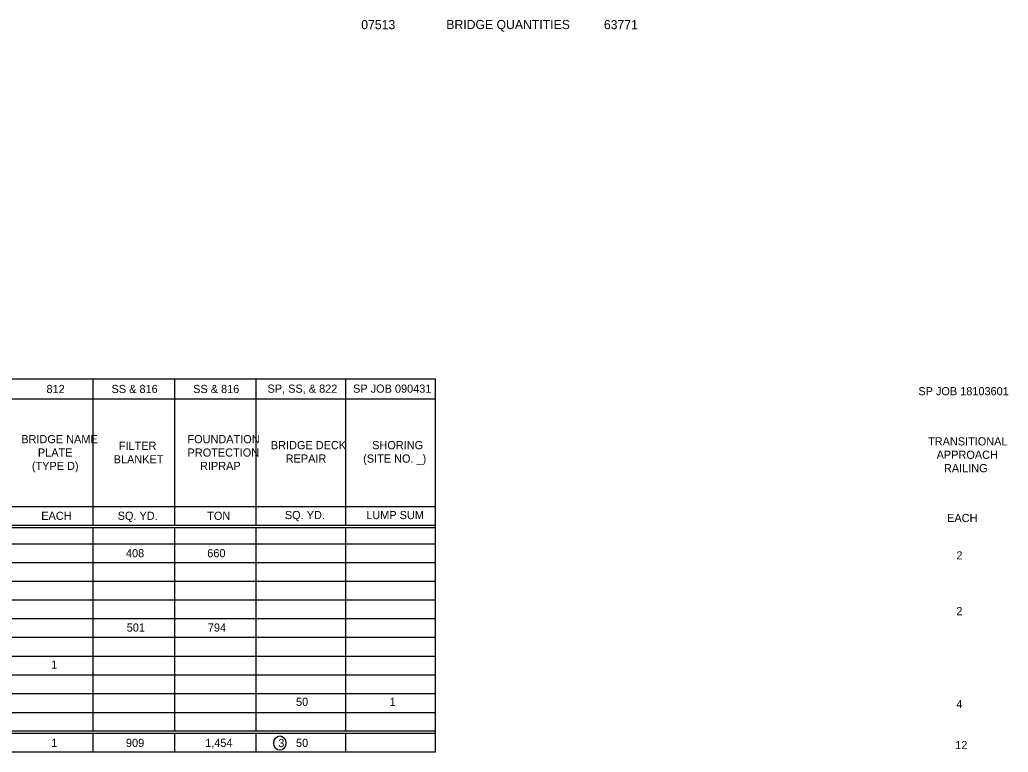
# Model space of a CAD drawing. Extents: x 1667526.8 to 1667564.8, y 551427.6 to 551446.9.
# Drawn here: x 1667545.82 to 1667560.96, y 551435.73 to 551446.94 of the extents above; entities that cross this region are included whole.
import ezdxf

# ---------------------------------------------------------------- set-up
doc = ezdxf.new("R2010")
doc.units = 0
doc.layers.add('Level 4', color=7, linetype='Continuous')
doc.layers.add('R_Border', color=7, linetype='Continuous')

msp = doc.modelspace()

# ---------------------------------------------------------------- linework, layer by layer
at = {"layer": 'Level 4'}
for p, q in [((1667552.188, 551441.439), (1667526.829, 551441.439)), ((1667546.945, 551439.206), (1667546.945, 551441.439)), ((1667548.195, 551439.206), (1667548.195, 551441.439)), ((1667549.445, 551439.206), (1667549.445, 551441.439)), ((1667550.816, 551439.206), (1667550.816, 551441.439)), ((1667552.188, 551435.729), (1667552.188, 551441.439)), ((1667530.881, 551441.142), (1667552.188, 551441.142)), ((1667531.616, 551439.493), (1667552.188, 551439.493)), ((1667526.829, 551439.206), (1667552.188, 551439.206)), ((1667526.829, 551439.168), (1667552.188, 551439.168)), ((1667546.945, 551436.054), (1667546.945, 551439.168)), ((1667548.195, 551436.054), (1667548.195, 551439.168)), ((1667549.445, 551436.054), (1667549.445, 551439.168)), ((1667550.816, 551436.054), (1667550.816, 551439.168)), ((1667527.984, 551438.92), (1667552.188, 551438.92)), ((1667527.984, 551438.633), (1667552.188, 551438.633)), ((1667527.984, 551438.347), (1667552.188, 551438.347)), ((1667527.984, 551438.06), (1667552.188, 551438.06)), ((1667552.188, 551437.773), (1667527.984, 551437.773)), ((1667552.188, 551437.487), (1667527.984, 551437.487)), ((1667527.984, 551437.2), (1667552.188, 551437.2)), ((1667527.984, 551436.914), (1667552.188, 551436.914)), ((1667527.984, 551436.627), (1667552.188, 551436.627)), ((1667527.984, 551436.34), (1667552.188, 551436.34)), ((1667552.188, 551436.054), (1667526.829, 551436.054)), ((1667552.188, 551436.016), (1667528.635, 551436.016)), ((1667546.945, 551435.729), (1667546.945, 551436.016)), ((1667548.195, 551435.729), (1667548.195, 551436.016)), ((1667549.445, 551435.729), (1667549.445, 551436.016)), ((1667550.816, 551435.729), (1667550.816, 551436.016)), ((1667552.188, 551435.729), (1667526.829, 551435.729))]:
    msp.add_line(p, q, dxfattribs=at)
msp.add_ellipse((1667549.806, 551435.869), major_axis=(0, 0.11), ratio=0.84, dxfattribs=at)

# ---------------------------------------------------------------- texts
for s, p in [('812', (1667546.232, 551441.228)), ('SS & 816', (1667547.228, 551441.228)), ('SS & 816', (1667548.478, 551441.228)), ('SP, SS, & 822', (1667549.617, 551441.233)), ('SP JOB 090431', (1667550.927, 551441.233)), ('SP JOB 18103601', (1667559.583, 551441.194)), ('BRIDGE NAME', (1667545.846, 551440.46)), ('FOUNDATION', (1667548.391, 551440.46)), ('TRANSITIONAL', (1667559.732, 551440.426)), ('PLATE', (1667546.101, 551440.255)), ('FILTER', (1667547.34, 551440.358)), ('PROTECTION', (1667548.392, 551440.255)), ('BRIDGE DECK', (1667549.668, 551440.368)), ('SHORING', (1667551.219, 551440.368)), ('BLANKET', (1667547.261, 551440.152)), ('REPAIR', (1667549.895, 551440.163)), ('(SITE NO. _)', (1667551.081, 551440.163)), ('APPROACH', (1667559.863, 551440.221)), ('(TYPE D)', (1667546.008, 551440.05)), ('RIPRAP', (1667548.583, 551440.05)), ('RAILING', (1667559.975, 551440.016)), ('EACH', (1667546.152, 551439.287)), ('SQ. YD.', (1667547.322, 551439.287)), ('TON', (1667548.693, 551439.287)), ('SQ. YD.', (1667549.882, 551439.298)), ('LUMP SUM', (1667551.129, 551439.298)), ('EACH', (1667560.024, 551439.253)), ('408', (1667547.449, 551438.714)), ('660', (1667548.694, 551438.714)), ('2', (1667560.165, 551438.68)), ('2', (1667560.165, 551437.827)), ('501', (1667547.461, 551437.576)), ('794', (1667548.703, 551437.576)), ('1', (1667546.305, 551437.008)), ('50', (1667550.053, 551436.439)), ('1', (1667551.485, 551436.439)), ('4', (1667560.165, 551436.405)), ('1', (1667546.305, 551435.81)), ('909', (1667547.449, 551435.81)), ('1,454', (1667548.662, 551435.81)), ('3', (1667549.781, 551435.807)), ('50', (1667550.053, 551435.81)), ('12', (1667560.148, 551435.777))]:
    msp.add_text(s, height=0.125, dxfattribs=at).set_placement(p)
at = {"layer": 'R_Border'}
for s, p in [('07513', (1667551.052, 551446.798)), ('BRIDGE QUANTITIES', (1667552.354, 551446.8)), ('63771', (1667554.767, 551446.798))]:
    msp.add_text(s, height=0.14, rotation=0, dxfattribs=at).set_placement(p)

doc.saveas('drawing.dxf')
